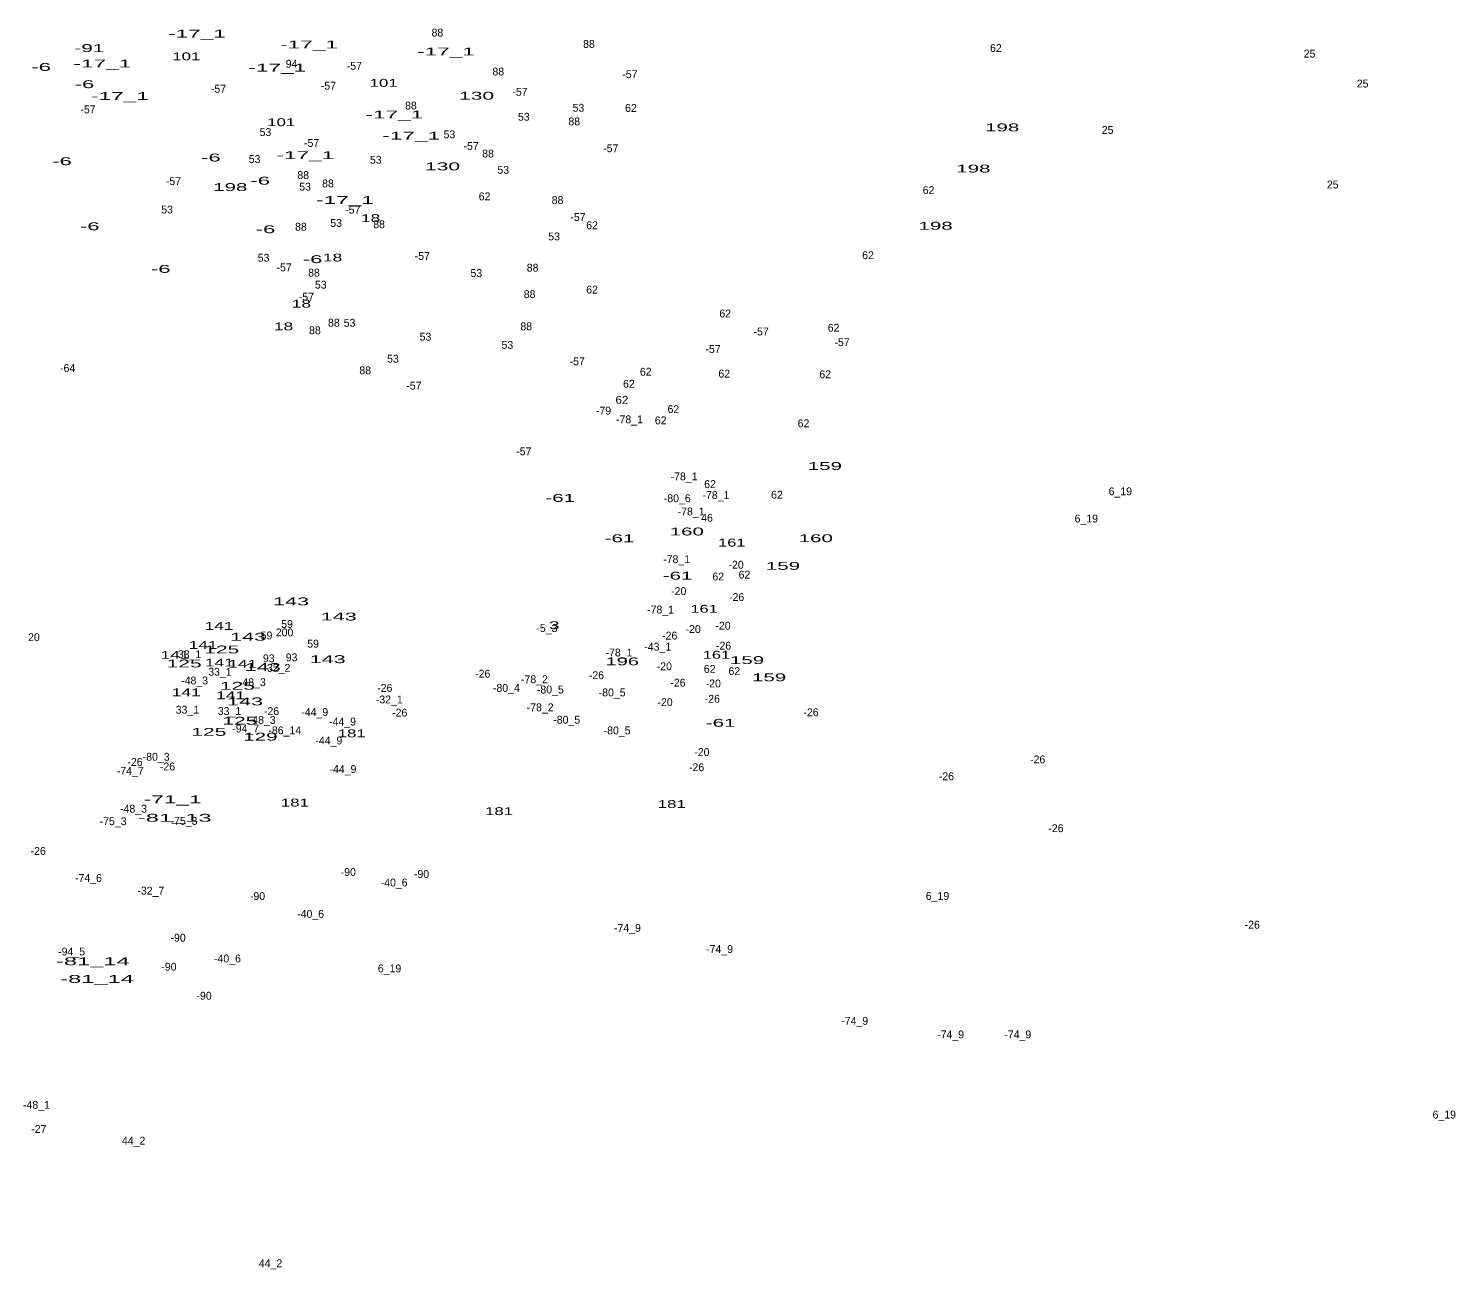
# Model space of a CAD drawing. Extents: x -659624 to -656248, y -1006345 to -1003555.
# Drawn here: x -657087 to -656361, y -1004869 to -1004238 of the extents above; entities that cross this region are included whole.
import ezdxf
from ezdxf.enums import TextEntityAlignment as Align

# ---------------------------------------------------------------- set-up
doc = ezdxf.new("R2010")
doc.units = 0
doc.header["$LTSCALE"] = 1.6
doc.layers.add('24', color=7, linetype='Continuous')

msp = doc.modelspace()

# ---------------------------------------------------------------- texts
at = {"layer": '24'}
for s, width, p in [('-17_1', 2.15, (-657001.563, -1004242.49)), ('-91', 1.95, (-657056.285, -1004249.86)), ('-17_1', 2.15, (-656944.503, -1004248.01)), ('-17_1', 2.15, (-656874.903, -1004251.62)), ('-6', 2.1, (-657080.809, -1004259.46)), ('-17_1', 2.15, (-657049.683, -1004257.71)), ('101', 1.6, (-657006.96, -1004254.08)), ('-17_1', 2.15, (-656960.683, -1004259.81)), ('-6', 2.1, (-657058.749, -1004268.22)), ('101', 1.6, (-656906.6, -1004267.55)), ('-17_1', 2.15, (-657040.743, -1004274.27)), ('130', 2, (-656859.344, -1004274.08)), ('101', 1.6, (-656958.71, -1004287.55)), ('-17_1', 2.15, (-656901.153, -1004283.65)), ('198', 1.95, (-656592.003, -1004290.22)), ('-17_1', 2.15, (-656892.593, -1004294.43)), ('-17_1', 2.15, (-656946.413, -1004304.33)), ('-6', 2.1, (-657070.159, -1004307.41)), ('-6', 2.1, (-656994.449, -1004305.54)), ('130', 2, (-656876.654, -1004310.04)), ('198', 1.95, (-656606.643, -1004311.15)), ('-6', 2.1, (-656969.349, -1004317.33)), ('198', 1.95, (-656984.603, -1004320.57)), ('-17_1', 2.15, (-656926.253, -1004327.15)), ('-6', 2.1, (-657056.079, -1004340.51)), ('18', 1.65, (-656913.207, -1004336.36)), ('198', 1.95, (-656625.853, -1004340.26)), ('-6', 2.1, (-656966.679, -1004342.03)), ('-6', 2.1, (-657019.949, -1004362.2)), ('-6', 2.1, (-656942.719, -1004357.25)), ('18', 1.65, (-656932.567, -1004356.42)), ('18', 1.65, (-656948.447, -1004379.89)), ('18', 1.65, (-656957.487, -1004391.43)), ('62', 1.1, (-656785.41, -1004428.8)), ('159', 1.95, (-656682.203, -1004462.49)), ('-61', 1.95, (-656816.795, -1004478.7)), ('-61', 1.95, (-656786.645, -1004499.24)), ('160', 1.95, (-656752.399, -1004495.79)), ('160', 1.95, (-656686.789, -1004499.21)), ('161', 1.55, (-656729.519, -1004501.43)), ('159', 1.95, (-656703.503, -1004513.29)), ('-61', 1.95, (-656757.085, -1004518.26)), ('143', 2.05, (-656953.683, -1004531.36)), ('161', 1.55, (-656743.589, -1004535.1)), ('141', 1.65, (-656990.339, -1004543.83)), ('143', 2.05, (-656929.433, -1004539.06)), ('3', 1.8, (-656819.831, -1004543.5)), ('143', 2.05, (-656975.553, -1004549.34)), ('141', 1.65, (-657012.679, -1004558.57)), ('141', 1.65, (-656998.419, -1004553.53)), ('125', 2, (-656988.937, -1004555.81)), ('161', 1.55, (-656737.319, -1004558.5)), ('125', 2, (-657008.067, -1004562.93)), ('141', 1.65, (-656990.149, -1004562.47)), ('141', 1.65, (-656978.259, -1004563.12)), ('143', 2.05, (-656968.053, -1004564.75)), ('143', 2.05, (-656935.053, -1004560.75)), ('196', 1.9, (-656785.217, -1004561.87)), ('159', 1.95, (-656721.763, -1004561.23)), ('159', 1.95, (-656710.543, -1004569.99)), ('141', 1.65, (-657006.989, -1004577.6)), ('141', 1.65, (-656984.439, -1004579.12)), ('125', 2, (-656980.957, -1004574.28)), ('143', 2.05, (-656977.083, -1004582.25)), ('125', 2, (-656979.707, -1004592.07)), ('-61', 1.95, (-656735.185, -1004593.13)), ('125', 2, (-656995.477, -1004597.74)), ('129', 1.95, (-656969.263, -1004600.18)), ('181', 1.6, (-656922.834, -1004598.49)), ('-71_1', 2.15, (-657013.893, -1004632.04)), ('181', 1.6, (-656951.734, -1004633.7)), ('181', 1.6, (-656847.904, -1004638.07)), ('181', 1.6, (-656760.044, -1004634.45)), ('-81_13', 2.25, (-657012.857, -1004641.44)), ('-81_14', 2.25, (-657054.503, -1004714.43)), ('-81_14', 2.25, (-657052.363, -1004723.41))]:
    msp.add_text(s, height=4, dxfattribs=dict(at, width=width)).set_placement(p, align=Align.CENTER)
for s, p in [('88', (-656879.257, -1004241.97)), ('88', (-656802.167, -1004247.74)), ('62', (-656595.193, -1004249.83)), ('25', (-656435.657, -1004252.68)), ('94', (-656953.427, -1004257.82)), ('-57', (-656921.491, -1004258.89)), ('88', (-656848.307, -1004261.78)), ('-57', (-656781.351, -1004263.15)), ('25', (-656408.647, -1004267.9)), ('-57', (-656990.591, -1004270.55)), ('-57', (-656934.691, -1004269)), ('-57', (-656837.251, -1004272.09)), ('-57', (-657056.981, -1004281.03)), ('88', (-656892.717, -1004279.09)), ('53', (-656807.527, -1004280.23)), ('62', (-656780.813, -1004280.31)), ('53', (-656835.297, -1004284.8)), ('88', (-656809.667, -1004287.17)), ('53', (-656966.707, -1004292.61)), ('53', (-656873.147, -1004293.74)), ('25', (-656538.357, -1004291.49)), ('-57', (-656943.231, -1004298.12)), ('-57', (-656862.101, -1004299.66)), ('88', (-656853.497, -1004303.51)), ('-57', (-656791.061, -1004300.83)), ('53', (-656972.237, -1004306.29)), ('53', (-656910.607, -1004306.68)), ('53', (-656845.757, -1004311.81)), ('-57', (-657013.501, -1004317.54)), ('88', (-656947.507, -1004314.48)), ('88', (-656934.917, -1004318.71)), ('53', (-656946.557, -1004320.37)), ('62', (-656855.253, -1004325.3)), ('62', (-656629.423, -1004322.12)), ('25', (-656423.867, -1004319.27)), ('53', (-657016.747, -1004331.98)), ('-57', (-656922.271, -1004332.09)), ('88', (-656818.137, -1004327.17)), ('88', (-656948.667, -1004340.73)), ('53', (-656930.777, -1004338.83)), ('88', (-656908.937, -1004339.5)), ('-57', (-656807.751, -1004335.78)), ('62', (-656800.583, -1004340)), ('53', (-656819.897, -1004345.68)), ('62', (-656660.233, -1004355.22)), ('53', (-656967.667, -1004356.52)), ('-57', (-656957.211, -1004361.42)), ('-57', (-656886.941, -1004355.59)), ('88', (-656830.827, -1004361.59)), ('88', (-656942.027, -1004364.1)), ('53', (-656859.457, -1004364.32)), ('-57', (-656945.851, -1004376.37)), ('53', (-656938.577, -1004370.22)), ('88', (-656832.357, -1004375.05)), ('62', (-656800.583, -1004372.73)), ('88', (-656931.927, -1004389.58)), ('53', (-656923.927, -1004389.63)), ('88', (-656834.087, -1004391.4)), ('62', (-656732.883, -1004384.9)), ('88', (-656941.547, -1004393.42)), ('53', (-656885.317, -1004396.67)), ('-57', (-656714.581, -1004394.04)), ('62', (-656677.733, -1004392.13)), ('53', (-656843.667, -1004400.85)), ('-57', (-656739.041, -1004402.97)), ('-57', (-656673.431, -1004399.48)), ('-64', (-657067.315, -1004412.66)), ('53', (-656901.867, -1004407.89)), ('-57', (-656808.141, -1004409.18)), ('88', (-656915.977, -1004413.81)), ('62', (-656781.853, -1004420.66)), ('62', (-656773.293, -1004414.52)), ('62', (-656733.353, -1004415.47)), ('62', (-656682.003, -1004415.84)), ('-57', (-656891.211, -1004421.6)), ('-79', (-656794.765, -1004434.3)), ('62', (-656759.223, -1004433.55)), ('-78_1', (-656781.562, -1004438.72)), ('62', (-656765.683, -1004439.26)), ('62', (-656693.033, -1004440.78)), ('-57', (-656835.311, -1004455)), ('-78_1', (-656753.802, -1004467.76)), ('-80_6', (-656757.262, -1004478.87)), ('-78_1', (-656737.592, -1004477.27)), ('62', (-656740.583, -1004471.69)), ('62', (-656706.543, -1004477.09)), ('6_19', (-656531.9, -1004475.36)), ('-78_1', (-656750.212, -1004485.61)), ('46', (-656742.097, -1004488.82)), ('6_19', (-656549.2, -1004489.21)), ('-78_1', (-656757.592, -1004509.89)), ('-20', (-656727.319, -1004512.7)), ('62', (-656736.403, -1004518.69)), ('62', (-656723.083, -1004517.73)), ('-20', (-656756.509, -1004526.12)), ('-26', (-656727.05, -1004529.15)), ('-78_1', (-656765.752, -1004535.51)), ('59', (-656955.753, -1004542.87)), ('-20', (-656733.979, -1004543.71)), ('20', (-657084.471, -1004549.57)), ('59', (-656966.163, -1004548.67)), ('200', (-656956.985, -1004547.12)), ('-5_3', (-656823.583, -1004544.94)), ('-26', (-656761.09, -1004548.75)), ('-20', (-656749.189, -1004545.43)), ('33_1', (-657005.279, -1004558.21)), ('59', (-656942.483, -1004552.86)), ('-78_1', (-656786.902, -1004557.36)), ('-43_1', (-656767.17, -1004554.41)), ('-26', (-656733.71, -1004553.88)), ('93', (-656965.023, -1004560.31)), ('-32_2', (-656960.862, -1004565.15)), ('93', (-656953.403, -1004559.83)), ('-20', (-656763.829, -1004564.36)), ('62', (-656740.773, -1004565.68)), ('-48_3', (-657002.737, -1004571.59)), ('33_1', (-656989.869, -1004567.15)), ('-48_3', (-656973.357, -1004572.46)), ('-26', (-656856.19, -1004568.15)), ('-78_2', (-656829.908, -1004570.97)), ('-26', (-656798.37, -1004568.91)), ('-26', (-656756.91, -1004572.72)), ('-20', (-656738.919, -1004573.11)), ('62', (-656728.223, -1004566.82)), ('-26', (-656906.01, -1004575.38)), ('-80_4', (-656844.161, -1004575.37)), ('-80_5', (-656821.816, -1004576.2)), ('-80_5', (-656790.376, -1004577.66)), ('33_1', (-657006.419, -1004586.46)), ('33_1', (-656985.019, -1004587.13)), ('-26', (-656963.63, -1004587.18)), ('-44_9', (-656941.636, -1004587.65)), ('-32_1', (-656903.736, -1004581.24)), ('-78_2', (-656826.998, -1004585.24)), ('-20', (-656763.459, -1004582.62)), ('-26', (-656739.41, -1004580.9)), ('-26', (-656689.2, -1004587.76)), ('-48_3', (-656968.357, -1004591.67)), ('-44_9', (-656927.486, -1004592.5)), ('-26', (-656898.41, -1004587.94)), ('-80_5', (-656813.476, -1004591.54)), ('-94_7', (-656976.748, -1004595.99)), ('-86_14', (-656956.886, -1004596.95)), ('-44_9', (-656934.466, -1004602.1)), ('-80_5', (-656787.856, -1004596.98)), ('-20', (-656744.719, -1004608.02)), ('-26', (-657033.06, -1004613.04)), ('-80_3', (-657022.306, -1004610.4)), ('-26', (-657016.53, -1004615.34)), ('-44_9', (-656927.296, -1004616.65)), ('-26', (-656747.4, -1004615.71)), ('-26', (-656573.95, -1004611.73)), ('-74_7', (-657035.478, -1004617.58)), ('-26', (-656620.36, -1004620.3)), ('-48_3', (-657033.807, -1004636.82)), ('-75_3', (-657044.188, -1004643.19)), ('-75_3', (-657008.128, -1004643)), ('-26', (-656564.64, -1004646.74)), ('-26', (-657082.3, -1004658.32)), ('-74_6', (-657056.698, -1004672.05)), ('-90', (-656924.564, -1004669.05)), ('-40_6', (-656901.246, -1004674.35)), ('-90', (-656887.294, -1004670.02)), ('-32_7', (-657025.008, -1004678.5)), ('-90', (-656970.764, -1004681.29)), ('6_19', (-656624.9, -1004681.19)), ('-40_6', (-656943.736, -1004690.31)), ('-26', (-656464.79, -1004695.82)), ('-90', (-657011.134, -1004702.45)), ('-74_9', (-656782.588, -1004697.48)), ('-94_5', (-657065.312, -1004709.47)), ('-74_9', (-656735.738, -1004708.24)), ('-90', (-657015.794, -1004717.21)), ('-40_6', (-656986.026, -1004713.01)), ('6_19', (-656903.58, -1004718.05)), ('-90', (-656997.934, -1004731.97)), ('-74_9', (-656666.998, -1004744.73)), ('-74_9', (-656618.228, -1004751.65)), ('-74_9', (-656584.058, -1004751.65)), ('-48_1', (-657083.18, -1004787.47)), ('6_19', (-656367.14, -1004792.43)), ('-27', (-657081.991, -1004799.72)), ('44_2', (-657033.744, -1004805.66)), ('44_2', (-656964.134, -1004868.07))]:
    msp.add_text(s, height=4, dxfattribs=at).set_placement(p, align=Align.CENTER)

doc.saveas('drawing.dxf')
